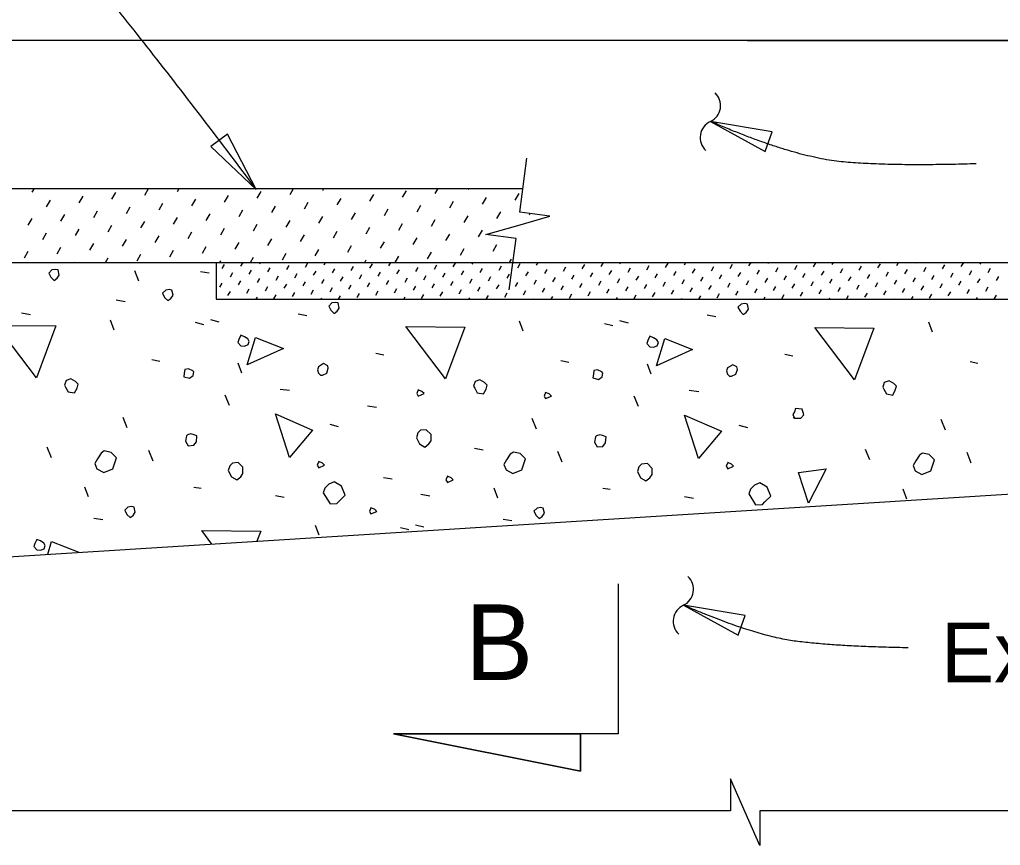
# Model space of a CAD drawing. Extents: x 0 to 41.1, y 0 to 25.9.
# Drawn here: x 9.677 to 12.993, y 6.378 to 9.169 of the extents above; entities that cross this region are included whole.
import ezdxf

# ---------------------------------------------------------------- set-up
doc = ezdxf.new("R2010")
doc.units = 0
for name, color, linetype in [('Dimension', 7, 'Continuous'), ('Miscellaneous', 7, 'Continuous'), ('TextStructures', 7, 'Continuous'), ('TrafBarrierConc', 7, 'Continuous')]:
    doc.layers.add(name, color=color, linetype=linetype)

msp = doc.modelspace()

# ---------------------------------------------------------------- linework, layer by layer
at = {"layer": 'Dimension'}
for p, q in [((11.7002, 7.2616), (11.7002, 6.7553)), ((11.7002, 6.7553), (10.9408, 6.7553)), ((10.9408, 6.7553), (11.5736, 6.6287)), ((11.5736, 6.6287), (11.5736, 6.7553))]:
    msp.add_line(p, q, dxfattribs=at)
for points in [[(12.0127, 8.8255), (12.1978, 8.7238), (12.221, 8.7904)], [(10.4769, 8.5946), (10.3801, 8.7824), (10.3237, 8.7401)], [(11.9212, 7.1903), (12.1064, 7.0886), (12.1295, 7.1552)], [(11.5736, 6.7553), (11.5736, 6.6287), (10.9408, 6.7553)]]:
    msp.add_lwpolyline(points, close=True, dxfattribs=at)
for points in [[(11.3325, 8.2555), (11.3557, 8.4293), (11.2532, 8.443), (11.3616, 8.4739), (11.47, 8.5049), (11.3676, 8.5185), (11.3919, 8.7009)], [(10.5811, 6.4942), (8.9649, 6.4942), (8.9649, 6.3779), (8.8655, 6.6029), (8.8655, 6.4942), (8.2103, 6.4942)], [(14.7437, 6.4942), (12.1798, 6.4942), (12.1798, 6.3779), (12.0804, 6.6029), (12.0804, 6.4942), (10.5811, 6.4942)]]:
    msp.add_lwpolyline(points, dxfattribs=at)
for centre, start, end in [((11.9873, 8.8787), 295.0115, 46.7387), ((12.0377, 8.7707), 115.0115, 226.7387), ((11.8958, 7.2435), 295.0115, 46.7387), ((11.9463, 7.1355), 115.0115, 226.7387)]:
    msp.add_arc(centre, 0.0596, start, end, dxfattribs=at)
for points in [[(7.3008, 10.4958), (7.6278, 10.4958), (8.1267, 10.4958), (9.0246, 10.2686), (9.7785, 9.5258), (10.4769, 8.5946)], [(12.9115, 8.6821), (12.6362, 8.6733), (12.2963, 8.7024), (12.0127, 8.8254)], [(12.6815, 7.0459), (12.436, 7.05), (12.1589, 7.0872), (11.9212, 7.1902)]]:
    msp.add_open_spline(points, degree=2, dxfattribs=at)
at = {"layer": 'Miscellaneous'}
for p, q in [((9.7189, 8.5856), (9.7266, 8.5989)), ((9.8295, 8.5986), (9.8297, 8.5989)), ((10.0996, 8.5756), (10.1126, 8.598)), ((10.2102, 8.5886), (10.2162, 8.5989)), ((10.591, 8.5787), (10.6027, 8.5989)), ((10.7016, 8.5916), (10.7058, 8.5989)), ((10.9717, 8.5687), (10.9847, 8.5911)), ((11.0823, 8.5817), (11.0923, 8.5989)), ((11.193, 8.5947), (11.1954, 8.5989)), ((9.7677, 8.5368), (9.7807, 8.5591)), ((9.8783, 8.5497), (9.8913, 8.5721)), ((9.989, 8.5627), (10.0019, 8.5851)), ((10.2591, 8.5398), (10.272, 8.5622)), ((10.3697, 8.5527), (10.3827, 8.5751)), ((10.4803, 8.5657), (10.4933, 8.5881)), ((10.7504, 8.5428), (10.7634, 8.5652)), ((10.8611, 8.5558), (10.874, 8.5782)), ((11.2418, 8.5458), (11.2548, 8.5682)), ((11.3524, 8.5588), (11.3654, 8.5812)), ((9.9272, 8.5009), (9.9401, 8.5233)), ((10.0378, 8.5138), (10.0508, 8.5362)), ((10.1484, 8.5268), (10.1614, 8.5492)), ((10.4185, 8.5039), (10.4315, 8.5263)), ((10.5292, 8.5169), (10.5421, 8.5393)), ((10.6398, 8.5298), (10.6528, 8.5522)), ((10.9099, 8.5069), (10.9229, 8.5293)), ((11.0205, 8.5199), (11.0335, 8.5423)), ((11.1312, 8.5329), (11.1441, 8.5552)), ((9.7059, 8.475), (9.7189, 8.4973)), ((9.8165, 8.4879), (9.8295, 8.5103)), ((10.1973, 8.478), (10.2102, 8.5004)), ((10.3079, 8.4909), (10.3209, 8.5133)), ((10.578, 8.468), (10.591, 8.4904)), ((10.6886, 8.481), (10.7016, 8.5034)), ((10.7993, 8.494), (10.8122, 8.5164)), ((11.0694, 8.4711), (11.0823, 8.4934)), ((11.18, 8.484), (11.193, 8.5064)), ((11.2906, 8.497), (11.3036, 8.5194)), ((11.4013, 8.5099), (11.4035, 8.5137)), ((9.8654, 8.4391), (9.8783, 8.4615)), ((9.976, 8.4521), (9.989, 8.4744)), ((10.0866, 8.465), (10.0996, 8.4874)), ((10.3567, 8.4421), (10.3697, 8.4645)), ((10.4674, 8.4551), (10.4803, 8.4775)), ((10.8481, 8.4451), (10.8611, 8.4675)), ((10.9587, 8.4581), (10.9717, 8.4805)), ((11.2288, 8.4352), (11.2418, 8.4576)), ((9.7547, 8.4261), (9.7677, 8.4485)), ((10.0248, 8.4032), (10.0378, 8.4256)), ((10.1355, 8.4162), (10.1484, 8.4386)), ((10.2461, 8.4291), (10.2591, 8.4515)), ((10.5162, 8.4062), (10.5292, 8.4286)), ((10.6268, 8.4192), (10.6398, 8.4416)), ((10.7375, 8.4322), (10.7504, 8.4546)), ((11.0076, 8.4093), (11.0205, 8.4316)), ((11.1182, 8.4222), (11.1312, 8.4446)), ((9.8036, 8.3773), (9.8165, 8.3997)), ((9.9142, 8.3903), (9.9272, 8.4126)), ((10.2949, 8.3803), (10.3079, 8.4027)), ((10.4056, 8.3933), (10.4185, 8.4157)), ((10.6757, 8.3704), (10.6886, 8.3928)), ((10.7863, 8.3833), (10.7993, 8.4057)), ((10.8969, 8.3963), (10.9099, 8.4187)), ((11.167, 8.3734), (11.18, 8.3958)), ((11.2777, 8.3863), (11.2906, 8.4087)), ((9.6929, 8.3643), (9.7059, 8.3867)), ((9.9674, 8.3489), (9.976, 8.3638)), ((10.0737, 8.3544), (10.0866, 8.3768)), ((10.1843, 8.3673), (10.1973, 8.3897)), ((10.457, 8.3489), (10.4674, 8.3668)), ((10.565, 8.3574), (10.578, 8.3798)), ((10.9466, 8.3489), (10.9587, 8.3698)), ((11.0564, 8.3604), (11.0694, 8.3828)), ((11.3331, 8.3489), (11.3395, 8.3599)), ((9.8643, 8.3489), (9.8654, 8.3508)), ((10.3539, 8.3489), (10.3567, 8.3539)), ((10.3616, 8.328), (10.3697, 8.342)), ((10.4251, 8.3361), (10.4325, 8.3489)), ((10.4886, 8.3442), (10.4913, 8.3489)), ((10.5163, 8.3165), (10.5244, 8.3305)), ((10.5797, 8.3247), (10.5878, 8.3386)), ((10.6432, 8.3328), (10.6513, 8.3467)), ((10.7067, 8.3409), (10.7114, 8.3489)), ((10.7344, 8.3132), (10.7425, 8.3272)), ((10.7979, 8.3213), (10.806, 8.3353)), ((10.8435, 8.3489), (10.8481, 8.3569)), ((10.8614, 8.3294), (10.8695, 8.3434)), ((10.9249, 8.3375), (10.9315, 8.3489)), ((11.0161, 8.3179), (11.0242, 8.3319)), ((11.0796, 8.326), (11.0877, 8.34)), ((11.1431, 8.3341), (11.1512, 8.3481)), ((11.2066, 8.3422), (11.2105, 8.3489)), ((11.2343, 8.3145), (11.2424, 8.3285)), ((11.2978, 8.3226), (11.3059, 8.3366)), ((11.3612, 8.3307), (11.3693, 8.3447)), ((11.4247, 8.3388), (11.4306, 8.3489)), ((11.4524, 8.3111), (11.4605, 8.3251)), ((11.5159, 8.3192), (11.524, 8.3332)), ((11.5794, 8.3273), (11.5875, 8.3413)), ((11.6429, 8.3354), (11.6507, 8.3489)), ((11.7064, 8.3435), (11.7095, 8.3489)), ((11.7341, 8.3158), (11.7422, 8.3298)), ((11.7976, 8.3239), (11.8057, 8.3379)), ((11.8611, 8.332), (11.8692, 8.346)), ((11.9246, 8.3401), (11.9297, 8.3489)), ((11.9523, 8.3124), (11.9604, 8.3264)), ((11.9881, 8.3482), (11.9885, 8.3489)), ((12.0158, 8.3205), (12.0239, 8.3345)), ((12.0793, 8.3286), (12.0874, 8.3426)), ((12.1427, 8.3367), (12.1498, 8.3489)), ((12.2062, 8.3448), (12.2086, 8.3489)), ((12.2339, 8.3171), (12.242, 8.3311)), ((12.2974, 8.3252), (12.3055, 8.3392)), ((12.3609, 8.3333), (12.369, 8.3473)), ((12.4244, 8.3414), (12.4287, 8.3489)), ((12.4521, 8.3138), (12.4602, 8.3277)), ((12.5156, 8.3219), (12.5237, 8.3358)), ((12.5791, 8.33), (12.5872, 8.344)), ((12.6426, 8.3381), (12.6489, 8.3489)), ((12.6703, 8.3104), (12.6784, 8.3244)), ((12.7061, 8.3462), (12.7077, 8.3489)), ((12.7338, 8.3185), (12.7419, 8.3325)), ((12.7973, 8.3266), (12.8054, 8.3406)), ((12.8608, 8.3347), (12.8689, 8.3487)), ((12.9242, 8.3428), (12.9278, 8.3489)), ((12.9519, 8.3151), (12.96, 8.3291)), ((10.08, 8.285), (10.0659, 8.3204)), ((10.288, 8.3182), (10.318, 8.3129)), ((10.3893, 8.3003), (10.3974, 8.3143)), ((10.4528, 8.3084), (10.4609, 8.3224)), ((10.4805, 8.2808), (10.4886, 8.2947)), ((10.5439, 8.2889), (10.552, 8.3028)), ((10.6074, 8.297), (10.6155, 8.311)), ((10.6709, 8.3051), (10.679, 8.3191)), ((10.6986, 8.2774), (10.7067, 8.2914)), ((10.7621, 8.2855), (10.7702, 8.2995)), ((10.8256, 8.2936), (10.8337, 8.3076)), ((10.8891, 8.3017), (10.8972, 8.3157)), ((10.9526, 8.3098), (10.9607, 8.3238)), ((10.9803, 8.2821), (10.9884, 8.2961)), ((11.0438, 8.2902), (11.0519, 8.3042)), ((11.1073, 8.2983), (11.1154, 8.3123)), ((11.1708, 8.3064), (11.1789, 8.3204)), ((11.1985, 8.2787), (11.2066, 8.2927)), ((11.262, 8.2868), (11.2701, 8.3008)), ((11.3254, 8.2949), (11.3335, 8.3089)), ((11.3889, 8.303), (11.397, 8.317)), ((11.4801, 8.2834), (11.4882, 8.2974)), ((11.5436, 8.2915), (11.5517, 8.3055)), ((11.6071, 8.2996), (11.6152, 8.3136)), ((11.6706, 8.3077), (11.6787, 8.3217)), ((11.6983, 8.28), (11.7064, 8.294)), ((11.7618, 8.2881), (11.7699, 8.3021)), ((11.8253, 8.2962), (11.8334, 8.3102)), ((11.8888, 8.3043), (11.8969, 8.3183)), ((11.98, 8.2847), (11.9881, 8.2987)), ((12.0435, 8.2928), (12.0516, 8.3068)), ((12.1069, 8.3009), (12.115, 8.3149)), ((12.1704, 8.309), (12.1785, 8.323)), ((12.1981, 8.2813), (12.2062, 8.2953)), ((12.2616, 8.2894), (12.2697, 8.3034)), ((12.3251, 8.2975), (12.3332, 8.3115)), ((12.3886, 8.3056), (12.3967, 8.3196)), ((12.4163, 8.278), (12.4244, 8.2919)), ((12.4798, 8.2861), (12.4879, 8.3001)), ((12.5433, 8.2942), (12.5514, 8.3082)), ((12.6068, 8.3023), (12.6149, 8.3163)), ((12.698, 8.2827), (12.7061, 8.2967)), ((12.7615, 8.2908), (12.7696, 8.3048)), ((12.825, 8.2989), (12.8331, 8.3129)), ((12.8884, 8.307), (12.8965, 8.321)), ((12.9161, 8.2793), (12.9242, 8.2933)), ((12.9796, 8.2874), (12.9877, 8.3014)), ((10.3535, 8.2645), (10.3616, 8.2785)), ((10.417, 8.2727), (10.4251, 8.2866)), ((10.4447, 8.245), (10.4528, 8.259)), ((10.5081, 8.2531), (10.5163, 8.2671)), ((10.5716, 8.2612), (10.5797, 8.2752)), ((10.6351, 8.2693), (10.6432, 8.2833)), ((10.7263, 8.2497), (10.7344, 8.2637)), ((10.7898, 8.2578), (10.7979, 8.2718)), ((10.8533, 8.2659), (10.8614, 8.2799)), ((10.9168, 8.274), (10.9249, 8.288)), ((10.9445, 8.2463), (10.9526, 8.2603)), ((11.008, 8.2544), (11.0161, 8.2684)), ((11.0715, 8.2625), (11.0796, 8.2765)), ((11.135, 8.2706), (11.1431, 8.2846)), ((11.2262, 8.251), (11.2343, 8.265)), ((11.2896, 8.2591), (11.2978, 8.2731)), ((11.3531, 8.2672), (11.3612, 8.2812)), ((11.4166, 8.2753), (11.4247, 8.2893)), ((11.4443, 8.2476), (11.4524, 8.2616)), ((11.5078, 8.2557), (11.5159, 8.2697)), ((11.5713, 8.2638), (11.5794, 8.2778)), ((11.6348, 8.2719), (11.6429, 8.2859)), ((11.6625, 8.2442), (11.6706, 8.2582)), ((11.726, 8.2523), (11.7341, 8.2663)), ((11.7895, 8.2604), (11.7976, 8.2744)), ((11.853, 8.2685), (11.8611, 8.2825)), ((11.9165, 8.2766), (11.9246, 8.2906)), ((11.9442, 8.2489), (11.9523, 8.2629)), ((12.0077, 8.257), (12.0158, 8.271)), ((12.0711, 8.2651), (12.0793, 8.2791)), ((12.1346, 8.2732), (12.1427, 8.2872)), ((12.1623, 8.2455), (12.1704, 8.2595)), ((12.2258, 8.2536), (12.2339, 8.2676)), ((12.2893, 8.2617), (12.2974, 8.2757)), ((12.3528, 8.2699), (12.3609, 8.2838)), ((12.444, 8.2503), (12.4521, 8.2643)), ((12.5075, 8.2584), (12.5156, 8.2724)), ((12.571, 8.2665), (12.5791, 8.2805)), ((12.6345, 8.2746), (12.6426, 8.2886)), ((12.6622, 8.2469), (12.6703, 8.2609)), ((12.7257, 8.255), (12.7338, 8.269)), ((12.7892, 8.2631), (12.7973, 8.2771)), ((12.8527, 8.2712), (12.8608, 8.2852)), ((12.9438, 8.2516), (12.9519, 8.2656)), ((10.3812, 8.2369), (10.3893, 8.2508)), ((10.4762, 8.2239), (10.4805, 8.2313)), ((10.5358, 8.2254), (10.5439, 8.2394)), ((10.5993, 8.2335), (10.6074, 8.2475)), ((10.6628, 8.2416), (10.6709, 8.2556)), ((10.6963, 8.2239), (10.6986, 8.2279)), ((10.7551, 8.2239), (10.7621, 8.236)), ((10.8175, 8.2301), (10.8256, 8.2441)), ((10.881, 8.2382), (10.8891, 8.2522)), ((10.9753, 8.2239), (10.9803, 8.2326)), ((11.0357, 8.2267), (11.0438, 8.2407)), ((11.0992, 8.2348), (11.1073, 8.2488)), ((11.1627, 8.2429), (11.1708, 8.2569)), ((11.1954, 8.2239), (11.1985, 8.2292)), ((11.2542, 8.2239), (11.262, 8.2373)), ((11.3173, 8.2314), (11.3254, 8.2454)), ((11.3808, 8.2395), (11.3889, 8.2535)), ((11.4155, 8.2239), (11.4166, 8.2258)), ((11.4743, 8.2239), (11.4801, 8.2339)), ((11.5355, 8.228), (11.5436, 8.242)), ((11.599, 8.2361), (11.6071, 8.2501)), ((11.6945, 8.2239), (11.6983, 8.2305)), ((11.7537, 8.2246), (11.7618, 8.2386)), ((11.8172, 8.2327), (11.8253, 8.2467)), ((11.8807, 8.2408), (11.8888, 8.2548)), ((11.9146, 8.2239), (11.9165, 8.2271)), ((11.9734, 8.2239), (11.98, 8.2352)), ((12.0354, 8.2293), (12.0435, 8.2433)), ((12.0988, 8.2374), (12.1069, 8.2514)), ((12.1935, 8.2239), (12.1981, 8.2318)), ((12.2535, 8.226), (12.2616, 8.2399)), ((12.317, 8.2341), (12.3251, 8.248)), ((12.3805, 8.2422), (12.3886, 8.2562)), ((12.4137, 8.2239), (12.4163, 8.2285)), ((12.4725, 8.2239), (12.4798, 8.2366)), ((12.5352, 8.2307), (12.5433, 8.2447)), ((12.5987, 8.2388), (12.6068, 8.2528)), ((12.6338, 8.2239), (12.6345, 8.2251)), ((12.6926, 8.2239), (12.698, 8.2332)), ((12.7534, 8.2273), (12.7615, 8.2413)), ((12.8169, 8.2354), (12.825, 8.2494)), ((12.8803, 8.2435), (12.8884, 8.2575)), ((12.9127, 8.2239), (12.9161, 8.2298)), ((12.9715, 8.2239), (12.9796, 8.2379)), ((10.0036, 8.222), (10.0337, 8.2167)), ((10.9165, 8.2239), (10.9168, 8.2245)), ((9.6833, 8.178), (9.7133, 8.1727)), ((10.618, 8.1744), (10.648, 8.1691)), ((12.0013, 8.1709), (12.0313, 8.1656)), ((9.9966, 8.1196), (9.9842, 8.1532)), ((10.2706, 8.1461), (10.2989, 8.1391)), ((10.3223, 8.1554), (10.3506, 8.1483)), ((11.3799, 8.1161), (11.3675, 8.1497)), ((11.6539, 8.1426), (11.6822, 8.1355)), ((11.7056, 8.1519), (11.7339, 8.1448)), ((12.7632, 8.1125), (12.7508, 8.1461)), ((10.8814, 8.0418), (10.9079, 8.0365)), ((12.2646, 8.0383), (12.2912, 8.033)), ((10.1239, 8.0206), (10.1504, 8.0153)), ((10.4284, 7.9742), (10.416, 8.0078)), ((11.5072, 8.0171), (11.5337, 8.0118)), ((11.8117, 7.9707), (11.7993, 8.0043)), ((12.8904, 8.0136), (12.917, 8.0082)), ((10.386, 7.8646), (10.3718, 7.9)), ((10.5579, 7.9199), (10.5897, 7.9163)), ((11.7692, 7.8611), (11.7551, 7.8964)), ((11.9411, 7.9163), (11.973, 7.9128)), ((10.8533, 7.8643), (10.8833, 7.859)), ((10.0408, 7.789), (10.0267, 7.8244)), ((10.7258, 7.8014), (10.7541, 7.7943)), ((11.4241, 7.7855), (11.4099, 7.8209)), ((12.1091, 7.7979), (12.1374, 7.7908)), ((12.8074, 7.782), (12.7932, 7.8173)), ((9.7845, 7.6883), (9.7703, 7.7236)), ((10.1279, 7.6772), (10.1137, 7.7126)), ((11.2143, 7.7206), (11.2443, 7.7153)), ((11.5111, 7.6737), (11.497, 7.7091)), ((12.551, 7.6812), (12.5369, 7.7166)), ((12.8944, 7.6702), (12.8803, 7.7055)), ((10.9066, 7.6221), (10.9367, 7.6168)), ((9.91, 7.5557), (9.8976, 7.5893)), ((10.2657, 7.5888), (10.2905, 7.5853)), ((11.0338, 7.5647), (11.0638, 7.5594)), ((11.2933, 7.5522), (11.2809, 7.5858)), ((11.649, 7.5853), (11.6738, 7.5818)), ((12.6765, 7.5486), (12.6642, 7.5822)), ((10.5415, 7.5606), (10.5716, 7.5553)), ((11.9248, 7.557), (11.9548, 7.5517)), ((9.9281, 7.4845), (9.9582, 7.4792)), ((11.0157, 7.462), (11.044, 7.4549)), ((11.3114, 7.481), (11.3414, 7.4757)), ((10.69, 7.4262), (10.6776, 7.4598)), ((10.964, 7.4527), (10.9923, 7.4457))]:
    msp.add_line(p, q, dxfattribs=at)
for points in [[(9.7826, 8.2986), (9.7932, 8.2879), (9.8038, 8.295), (9.8109, 8.3056), (9.8074, 8.3233), (9.7985, 8.3251), (9.7861, 8.3233), (9.7755, 8.3127), (9.7826, 8.2986)], [(10.1671, 8.2304), (10.1777, 8.2198), (10.1883, 8.2269), (10.1954, 8.2375), (10.1918, 8.2552), (10.183, 8.2569), (10.1706, 8.2552), (10.16, 8.2446), (10.1671, 8.2304)], [(10.7293, 8.1868), (10.74, 8.1762), (10.7506, 8.1833), (10.7576, 8.1939), (10.7541, 8.2115), (10.7453, 8.2133), (10.7329, 8.2115), (10.7223, 8.2009), (10.7293, 8.1868)], [(12.1126, 8.1833), (12.1232, 8.1727), (12.1338, 8.1797), (12.1409, 8.1903), (12.1374, 8.208), (12.1285, 8.2098), (12.1162, 8.208), (12.1056, 8.1974), (12.1126, 8.1833)], [(9.7332, 7.9588), (9.5989, 8.1355), (9.7986, 8.1338), (9.7332, 7.9588)], [(11.1165, 7.9552), (10.9821, 8.132), (11.1819, 8.1302), (11.1165, 7.9552)], [(12.4998, 7.9517), (12.3654, 8.1285), (12.5652, 8.1267), (12.4998, 7.9517)], [(10.4248, 8.067), (10.4372, 8.0653), (10.4496, 8.0706), (10.4531, 8.0812), (10.4478, 8.09), (10.4372, 8.0971), (10.4248, 8.1024), (10.4178, 8.0882), (10.4142, 8.0776), (10.4248, 8.067)], [(10.4465, 8.0029), (10.4748, 8.0949), (10.5685, 8.0577), (10.4465, 8.0029)], [(11.8081, 8.0635), (11.8205, 8.0617), (11.8329, 8.067), (11.8364, 8.0776), (11.8311, 8.0865), (11.8205, 8.0935), (11.8081, 8.0988), (11.8011, 8.0847), (11.7975, 8.0741), (11.8081, 8.0635)], [(11.8298, 7.9994), (11.8581, 8.0913), (11.9518, 8.0542), (11.8298, 7.9994)], [(10.694, 7.9676), (10.7011, 7.9676), (10.7152, 7.9747), (10.7205, 7.9906), (10.7187, 7.9994), (10.7046, 8.0065), (10.6869, 7.9959), (10.6834, 7.9853), (10.6869, 7.9747), (10.694, 7.9676)], [(12.0773, 7.9641), (12.0843, 7.9641), (12.0985, 7.9711), (12.1038, 7.987), (12.102, 7.9959), (12.0879, 8.0029), (12.0702, 7.9923), (12.0667, 7.9817), (12.0702, 7.9711), (12.0773, 7.9641)], [(10.2317, 7.9623), (10.2512, 7.957), (10.2635, 7.9658), (10.2653, 7.9782), (10.2618, 7.9817), (10.2476, 7.9888), (10.2353, 7.987), (10.2335, 7.9747), (10.2317, 7.9623)], [(11.615, 7.9588), (11.6344, 7.9534), (11.6468, 7.9623), (11.6486, 7.9747), (11.645, 7.9782), (11.6309, 7.9853), (11.6185, 7.9835), (11.6168, 7.9711), (11.615, 7.9588)], [(9.8322, 7.9269), (9.841, 7.911), (9.8623, 7.9075), (9.8711, 7.9234), (9.8746, 7.9375), (9.8658, 7.9464), (9.8499, 7.9552), (9.834, 7.9499), (9.8287, 7.934), (9.8322, 7.9269)], [(11.2155, 7.9234), (11.2243, 7.9075), (11.2455, 7.904), (11.2544, 7.9199), (11.2579, 7.934), (11.2491, 7.9428), (11.2332, 7.9517), (11.2172, 7.9464), (11.2119, 7.9305), (11.2155, 7.9234)], [(12.5988, 7.9199), (12.6076, 7.904), (12.6288, 7.9004), (12.6376, 7.9163), (12.6412, 7.9305), (12.6323, 7.9393), (12.6164, 7.9481), (12.6005, 7.9428), (12.5952, 7.9269), (12.5988, 7.9199)], [(11.0246, 7.8964), (11.0441, 7.9052), (11.037, 7.9123), (11.0246, 7.9176), (11.0193, 7.9052), (11.0246, 7.8964)], [(11.4553, 7.8882), (11.4748, 7.897), (11.4677, 7.9041), (11.4553, 7.9094), (11.45, 7.897), (11.4553, 7.8882)], [(10.5892, 7.6896), (10.5415, 7.8363), (10.667, 7.7815), (10.5892, 7.6896)], [(11.9725, 7.6861), (11.9248, 7.8328), (12.0503, 7.778), (11.9725, 7.6861)], [(12.2965, 7.8226), (12.3177, 7.8226), (12.3283, 7.8332), (12.323, 7.8527), (12.3, 7.8545), (12.2965, 7.8438), (12.2912, 7.835), (12.2965, 7.8226), (12.2929, 7.8262)], [(10.2375, 7.7444), (10.2463, 7.7285), (10.2657, 7.7303), (10.2746, 7.7426), (10.2764, 7.7621), (10.264, 7.7674), (10.2551, 7.7692), (10.2445, 7.7656), (10.241, 7.7621), (10.2375, 7.7444)], [(11.0182, 7.7562), (11.0289, 7.735), (11.0465, 7.7244), (11.0607, 7.735), (11.0677, 7.7456), (11.0677, 7.7668), (11.0518, 7.7827), (11.0324, 7.781), (11.0235, 7.7721), (11.0182, 7.7562)], [(11.6207, 7.7409), (11.6296, 7.725), (11.649, 7.7267), (11.6579, 7.7391), (11.6596, 7.7586), (11.6473, 7.7639), (11.6384, 7.7656), (11.6278, 7.7621), (11.6243, 7.7586), (11.6207, 7.7409)], [(9.9383, 7.6512), (9.9612, 7.6388), (9.9913, 7.6512), (10.0037, 7.6883), (9.986, 7.706), (9.963, 7.7113), (9.9524, 7.7042), (9.94, 7.6847), (9.9312, 7.6688), (9.9383, 7.6512)], [(11.3215, 7.6476), (11.3445, 7.6353), (11.3746, 7.6476), (11.387, 7.6847), (11.3693, 7.7024), (11.3463, 7.7077), (11.3357, 7.7007), (11.3233, 7.6812), (11.3145, 7.6653), (11.3215, 7.6476)], [(12.7048, 7.6441), (12.7278, 7.6317), (12.7579, 7.6441), (12.7702, 7.6812), (12.7526, 7.6989), (12.7296, 7.7042), (12.719, 7.6971), (12.7066, 7.6777), (12.6978, 7.6618), (12.7048, 7.6441)], [(10.3824, 7.6454), (10.393, 7.6242), (10.4107, 7.6136), (10.4248, 7.6242), (10.4319, 7.6348), (10.4319, 7.656), (10.416, 7.6719), (10.3966, 7.6702), (10.3877, 7.6613), (10.3824, 7.6454)], [(10.6882, 7.6543), (10.7077, 7.6631), (10.7006, 7.6702), (10.6882, 7.6755), (10.6829, 7.6631), (10.6882, 7.6543)], [(11.7657, 7.6419), (11.7763, 7.6207), (11.794, 7.6101), (11.8081, 7.6207), (11.8152, 7.6313), (11.8152, 7.6525), (11.7993, 7.6684), (11.7798, 7.6666), (11.771, 7.6578), (11.7657, 7.6419)], [(12.0715, 7.6507), (12.091, 7.6596), (12.0839, 7.6666), (12.0715, 7.6719), (12.0662, 7.6596), (12.0715, 7.6507)], [(12.3442, 7.5345), (12.3106, 7.6388), (12.4043, 7.6512), (12.3442, 7.5345)], [(10.7033, 7.5694), (10.7262, 7.5323), (10.7492, 7.534), (10.7581, 7.5429), (10.7775, 7.5623), (10.7651, 7.5924), (10.7404, 7.6065), (10.7227, 7.5995), (10.7086, 7.5853), (10.7033, 7.5694)], [(11.1231, 7.605), (11.1425, 7.6138), (11.1354, 7.6209), (11.1231, 7.6262), (11.1178, 7.6138), (11.1231, 7.605)], [(12.1422, 7.5659), (12.1652, 7.5287), (12.1882, 7.5305), (12.197, 7.5393), (12.2165, 7.5588), (12.2041, 7.5888), (12.1794, 7.603), (12.1617, 7.5959), (12.1475, 7.5818), (12.1422, 7.5659)], [(10.0395, 7.4969), (10.0501, 7.4863), (10.0607, 7.4934), (10.0678, 7.504), (10.0642, 7.5217), (10.0554, 7.5234), (10.043, 7.5217), (10.0324, 7.5111), (10.0395, 7.4969)], [(10.8646, 7.4983), (10.8841, 7.5071), (10.877, 7.5142), (10.8646, 7.5195), (10.8593, 7.5071), (10.8646, 7.4983)], [(11.4228, 7.4934), (11.4334, 7.4828), (11.444, 7.4899), (11.451, 7.5005), (11.4475, 7.5181), (11.4387, 7.5199), (11.4263, 7.5181), (11.4157, 7.5075), (11.4228, 7.4934)], [(10.3268, 7.3967), (10.2923, 7.4421), (10.492, 7.4404), (10.4793, 7.4063)], [(9.735, 7.3772), (9.7473, 7.3754), (9.7597, 7.3807), (9.7633, 7.3913), (9.758, 7.4001), (9.7473, 7.4072), (9.735, 7.4125), (9.7279, 7.3984), (9.7244, 7.3878), (9.735, 7.3772)], [(9.7717, 7.362), (9.7849, 7.405), (9.8768, 7.3686)]]:
    msp.add_lwpolyline(points, dxfattribs=at)
at = {"layer": 'TrafBarrierConc'}
for p, q in [((18.3647, 9.0989), (8.3411, 9.0989)), ((12.1382, 9.0989), (18.4751, 9.0989)), ((9.1092, 8.5989), (11.3783, 8.5989)), ((8.3411, 8.3489), (20.0548, 8.3489)), ((10.3412, 8.3489), (10.3412, 8.2239)), ((10.3412, 8.2239), (20.0548, 8.2239)), ((9.5611, 7.3489), (13.5611, 7.5989))]:
    msp.add_line(p, q, dxfattribs=at)

# ---------------------------------------------------------------- texts
at = {"layer": 'TextStructures'}
for s, height, p in [('B', 0.256, (11.1842, 6.9366)), ('Existing End Bent Wing Wall', 0.2016, (12.7924, 6.9296))]:
    msp.add_text(s, height=height, dxfattribs=at).set_placement(p)

doc.saveas('drawing.dxf')
